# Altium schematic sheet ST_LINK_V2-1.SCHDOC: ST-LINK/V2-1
size A4; DocumentNumber: MB1165; Revision: C.1; SheetNumber: 15; SheetTotal: 17; Project: STM32469I-EVAL
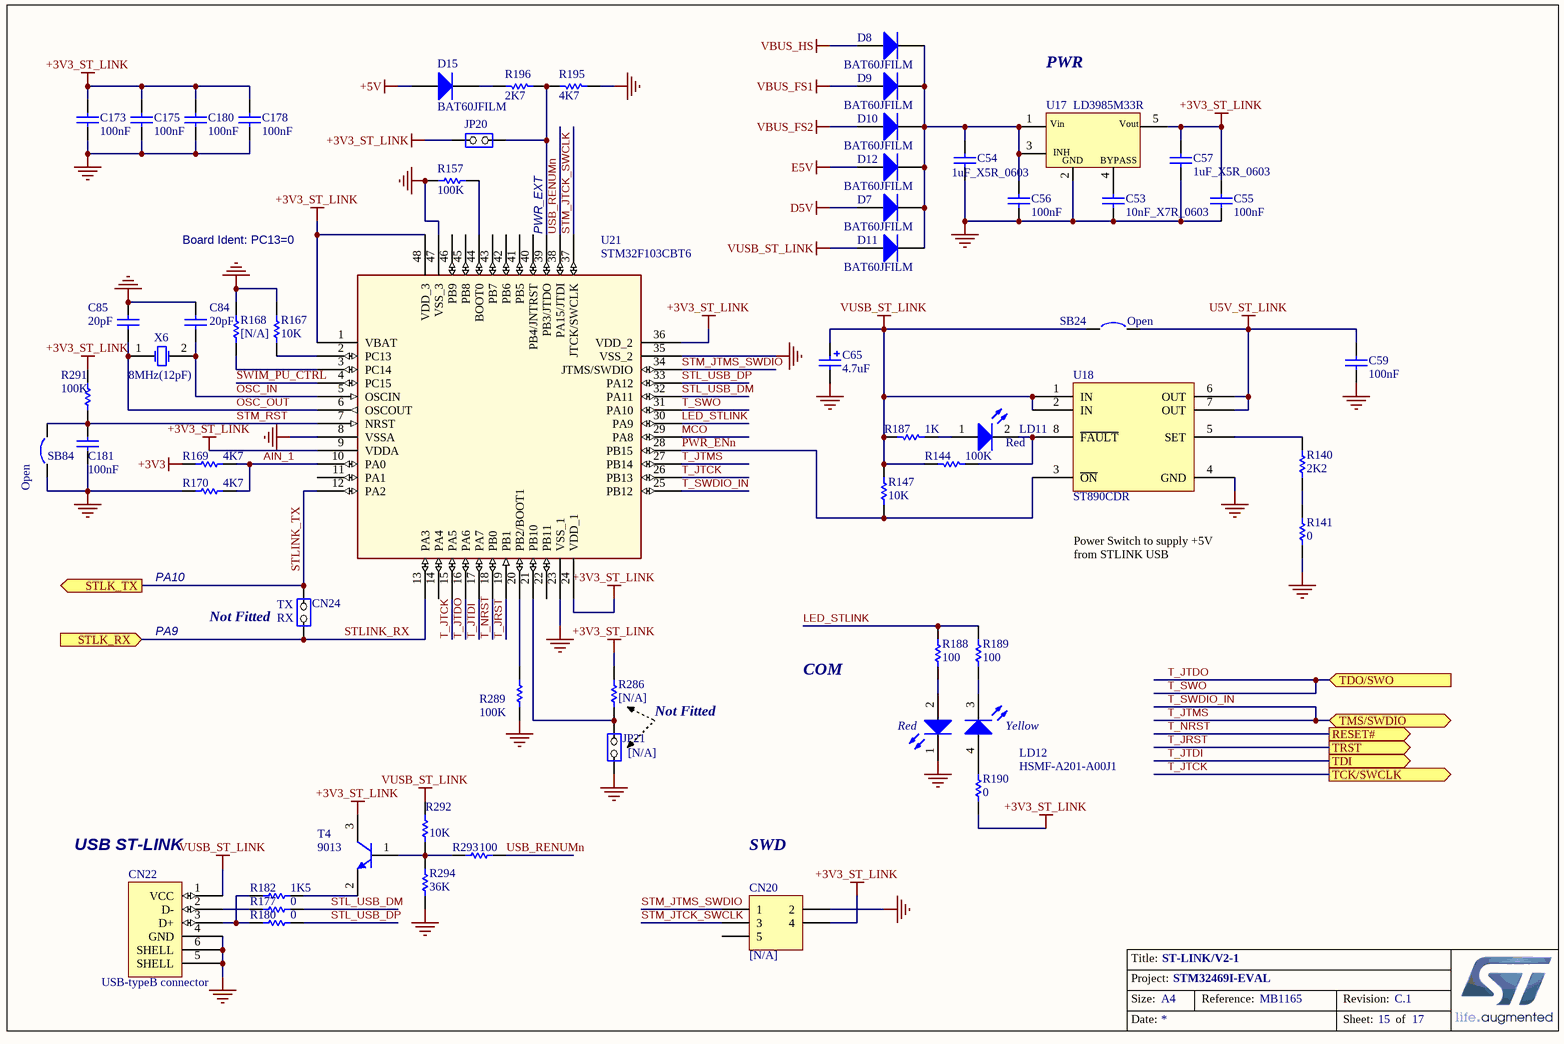
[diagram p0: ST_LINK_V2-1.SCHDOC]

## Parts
C53  10nF_X7R_0603  [0603C]
C54  1uF_X5R_0603  [0603C]
C55  100nF  [0603C]
C56  100nF  [0603C]
C57  1uF_X5R_0603  [0603C]
C59  100nF  [0603C]
C65  4.7uF  [TAN-A]
C84  20pF  [0603C]
C85  20pF  [0603C]
C173  100nF  [0603C]
C175  100nF  [0603C]
C178  100nF  [0603C]
C180  100nF  [0603C]
C181  100nF  [0603C]
CN20  [N/A]  [HDR_2X3-1_2R54-6]
CN22  USB-typeB connector  [USB-B]
CN24  (no value)  [SIP2]
D7  BAT60JFILM  [SOD-323]
D8  BAT60JFILM  [SOD-323]
D9  BAT60JFILM  [SOD-323]
D10  BAT60JFILM  [SOD-323]
D11  BAT60JFILM  [SOD-323]
D12  BAT60JFILM  [SOD-323]
D15  BAT60JFILM  [SOD-323]
JP20  (no value)  [SIP2]
JP21  [N/A]  [SIP2]
LD11  Red  [0603D]
LD12  HSMF-A201-A00J1  [LED2_3528]
R140  2K2  [0402R]
R141  0  [0603R]
R144  100K  [0603R]
R147  10K  [0402R]
R157  100K  [0603R]
R167  10K  [0603R]
R168  [N/A]  [0603R]
R169  4K7  [0603R]
R170  4K7  [0603R]
R177  0  [0603R]
R180  0  [0603R]
R182  1K5  [0603R]
R187  1K  [0603R]
R188  100  [0603R]
R189  100  [0603R]
R190  0  [0603R]
R195  4K7  [0603R]
R196  2K7  [0603R]
R286  [N/A]  [0603R]
R289  100K  [0603R]
R291  100K  [0603R]
R292  10K  [0603R]
R293  100  [0603R]
R294  36K  [0603R]
SB24  Open  [SB_0603]
SB84  Open  [SB_0603]
T4  9013  [SOT-23]
U17  LD3985M33R  [SOT23-5]
U18  ST890CDR  [SOIC8_1R27_4R9X6]
U21  STM32F103CBT6  [LQFP48_0R5_9X9]
X6  8MHz(12pF)  [XTAL_2SM_12R7X4R7]

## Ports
RESET# (out), STLK_RX (in), STLK_TX (out), TCK/SWCLK (out), TDI (out), TDO/SWO (in), TMS/SWDIO (bidir), TRST (out)

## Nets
+3V3: R169.1
+3V3_ST_LINK: C55.2 C57.1 C173.2 C175.2 C178.2 C180.2 CN20.4 JP20.1(COMMON) R190.2 R286.1 R291.2 T4.3(C) U17.5(Vout) U21.1(VBAT) U21.9(VDDA) U21.24(VDD_1) U21.36(VDD_2) U21.48(VDD_3)
+5V: D15.1(A)
D5V: D7.1(A)
E5V: D12.1(A)
GND: C53.1 C54.1 C55.1 C56.1 C57.2 C59.1 C65.2 C84.2 C85.2 C173.1 C175.1 C178.1 C180.1 C181.1 CN20.2 CN22.4(GND) CN22.5(SHELL) CN22.6(SHELL) JP21.1(COMMON) LD12.1(RED_cathode) R141.1 R157.1 R167.1 R168.1 R170.1 R195.2 R289.1 R294.1 SB84.1 U17.2(GND) U18.4(GND) U21.8(VSSA) U21.23(VSS_1) U21.35(VSS_2) U21.47(VSS_3)
U5V_ST_LINK: C59.2 SB24.2 U18.6(OUT) U18.7(OUT)
VBUS_FS1: D9.1(A)
VBUS_FS2: D10.1(A)
VBUS_HS: D8.1(A)
VUSB_ST_LINK: C65.1 CN22.1(VCC) D11.1(A) R144.1 R147.1 R187.1 R292.2 SB24.1 U18.1(IN) U18.2(IN)
AIN_1: R169.2 R170.2 U21.10(PA0)
LED_STLINK: R188.1 R189.1 U21.30(PA9)
MCO: U21.29(PA8)
OSC_IN: C84.1 U21.5(OSCIN) X6.2(OSC2)
OSC_OUT: C85.1 U21.6(OSCOUT) X6.1(OSC1)
PWR_ENn: R147.2 U18.3(~{ON}) U21.28(PB15)
STL_USB_DM: R177.2 U21.32(PA11)
STL_USB_DP: R180.2 U21.33(PA12)
STLINK_RX: CN24.1(COMMON) U21.13(PA3) ; port STLK_RX
STLINK_TX: CN24.2(NO) U21.12(PA2) ; port STLK_TX
STM_JTCK_SWCLK: CN20.3 U21.37(JTCK/SWCLK)
STM_JTMS_SWDIO: CN20.1 U21.34(JTMS/SWDIO)
STM_RST: C181.2 R291.1 SB84.2 U21.7(NRST)
SWIM_PU_CTRL: U21.4(PC15)
T_JRST: U21.19(PB1) ; port TRST
T_JTCK: U21.15(PA5) U21.26(PB13) ; port TCK/SWCLK
T_JTDI: U21.17(PA7) ; port TDI
T_JTDO: U21.16(PA6) U21.31(PA10) ; port TDO/SWO  [also labelled T_SWO]
T_JTMS: U21.25(PB12) U21.27(PB14) ; port TMS/SWDIO  [also labelled T_SWDIO_IN]
T_NRST: U21.18(PB0) ; port RESET#
USB_RENUMn: R293.2 U21.38(PA15/JTDI)
NetC53_2: C53.2 U17.4(BYPASS)
NetC54_2: C54.2 C56.2 D7.2(K) D8.2(K) D9.2(K) D10.2(K) D11.2(K) D12.2(K) U17.1(Vin) U17.3(CE)
NetCN22_2: CN22.2(D-) R177.1
NetCN22_3: CN22.3(D+) R180.1 R182.1
NetD15_2: D15.2(K) R196.1
NetJP20_2: JP20.2(NO) R195.1 R196.2 U21.39(PB3/JTDO)
NetJP21_2: JP21.2(NO) R286.2 U21.21(PB10)
NetLD11_1: LD11.1(A) R187.2
NetLD11_2: LD11.2(K) R144.2 U18.8(~{FAULT})
NetLD12_2: LD12.2(Red_anode) R188.2
NetLD12_3: LD12.3(YellowGreen_cathode) R189.2
NetLD12_4: LD12.4(YellowGreen_anode) R190.1
NetR140_1: R140.1 R141.2
NetR140_2: R140.2 U18.5(SET)
NetR157_2: R157.2 U21.44(BOOT0)
NetR167_2: R167.2 U21.2(PC13)
NetR168_2: R168.2 U21.3(PC14)
NetR182_2: R182.2 T4.2(E)
NetR289_2: R289.2 U21.20(PB2/BOOT1)
NetR292_1: R292.1 R293.1 R294.2 T4.1(B)

Not connected (* = marked no-connect by the designer): CN20 5; U21 11(PA1) 14(PA4) 22(PB11) 40(PB4/JNTRST) 41(PB5) 42(PB6) 43(PB7) 45(PB8) 46(PB9)

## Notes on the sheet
- PWR
- Board Ident: PC13=0
- (near U21) PWR_EXT
- PA10
- Power Switch to supply +5V from STLINK USB
- PA9
- (near CN24) Not Fitted
- (near CN24) TX
- (near CN24) RX
- Not Fitted
- COM
- (near CN22) USB ST-LINK
- SWD

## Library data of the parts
C53 = CAP SMD 0603  X7R 10000PF 50V 10%: 0603  X7R 10NF; Order code RS: 2040779; Rated voltage: 50V; Tolerance: 10%
C54 C57 = CAP SMD 0603  X5R 1µF 25V 10%: 0603  X5R 1µF; Rated voltage: 25V; Tolerance: 10%
C55 C56 C59 C173 C175 C178 C180 C181 = Capacitor_ST: Capacitor 0402 / 0603 / 0805
C65 = Cap Pol1: Polarized Capacitor (Radial); Value: 100pF; Ordered by: Subcon
C84 C85 = Capacitor_ST: Capacitor 0402 / 0603 / 0805; Value: 100nF
CN20 = Header 3X2: Header, 3-Pin, Dual row
CN24 = JP2: Fitted: NO
D7-D12 = BAT60JFILM: Manuf_1: STM; Provided: ST; ECCN_US/EU: EAR99/NEC
D15 = Diode: Default Diode; Code - JEDEC: DO-214-AB; Ordered by: STM; ECCN_US/EU: EAR99/NEC
JP20 = JP2: Ordered by: Subcon; Silkscreen: Pwr_ext
JP21 = JP2
LD11 = LED2: Typical RED, GREEN, YELLOW, AMBER GaAs LED
R140 R157 R177 R180 R182 R289 R291 R293 = Resistor_ST: Resistor 0402 / 0603 / 0805; Description: Resistor 0402 or 0603 or 0805; Value: 10K
R141 R188-R190 R195 R196 R286 R292 R294 = Res1: Resistor; Value: 1K
R144 = Res1: Resistor; Value: 1K; Ordered by: Subcon
R147 R167 = Resistor_ST: Resistor 0402 / 0603 / 0805; Description: Resistor 0402 or 0603 or 0805
R168-R170 = Resistor_ST: Resistor 0402 / 0603 / 0805; Description: Resistor 0402 or 0603 or 0805; Value: 10K; Fitted: NO
R187 = Res1: Resistor; Ordered by: Subcon
SB24 SB84 = Circuit Breaker
T4 = NPN: NPN Bipolar Transistor; Code - JEDEC: TO-226-AA
U17 = LD3985M33R: Ultra low drop-low noise BiCMOS voltage, regulators low ESR capacitors compatible; Manuf_1: STM; Provided: ST; Ref St: 9176161; ECCN_US/EU: EAR99/NEC
U21 = STM32F103CBT6: Medium-density performance line ARM-based 32-bit MCU with 64KB Flash; Manuf_Part_1: STM32F103C8T6; Manuf_1: STM; Ref St: 9175981; Provided: ST; ECCN_US/EU: 3A991A2/NEC
X6 = XTAL: Crystal Oscillator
